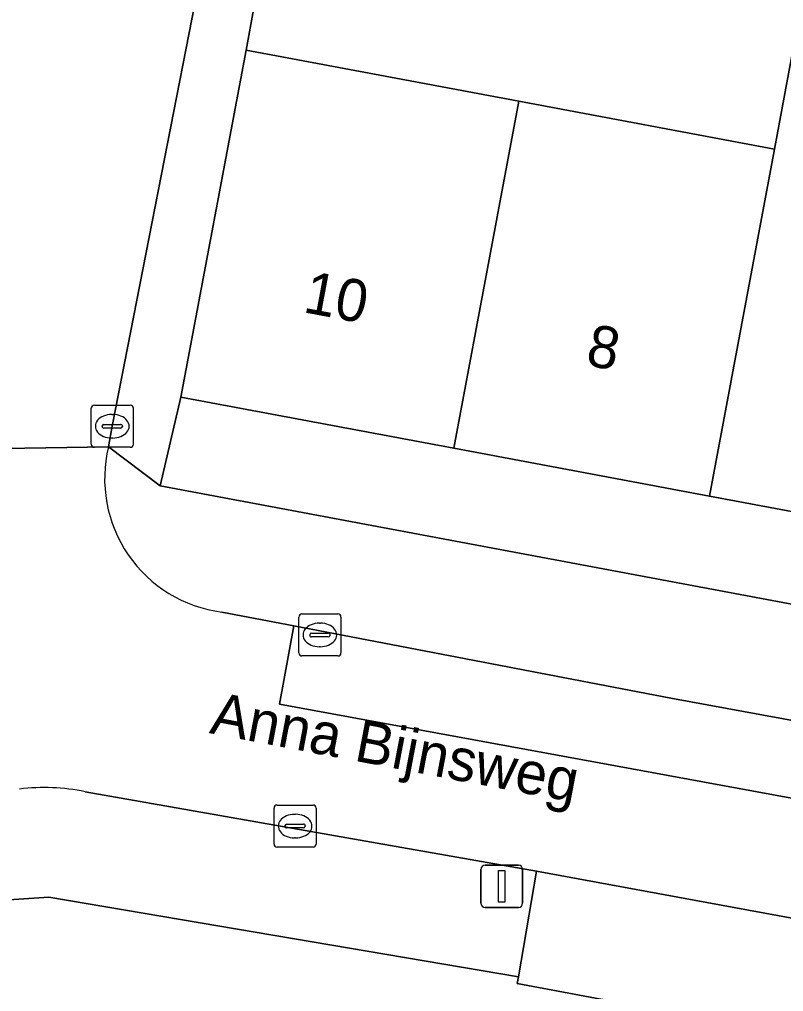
# Model space of a CAD drawing. Extents: x 161402 to 161933, y 381647 to 382315.
# Drawn here: x 161820.33 to 161838.49, y 381943.55 to 381966.66 of the extents above; entities that cross this region are included whole.
import ezdxf

# ---------------------------------------------------------------- set-up
doc = ezdxf.new("R2010")
doc.units = 0
for name, color, linetype in [('IMGEO_Erf', 7, 'Continuous'), ('IMGEO_Kolk', 7, 'Continuous'), ('IMGEO_Lichtmast', 7, 'Continuous'), ('IMGEO_Muur', 7, 'Continuous'), ('IMGEO_Openbare_ruimte_label', 7, 'Continuous'), ('IMGEO_Pand', 7, 'Continuous'), ('IMGEO_Pand_nummerreeks', 7, 'Continuous'), ('IMGEO_Parkeervlak_open', 7, 'Continuous'), ('IMGEO_Rijbaan_lokaal_open', 7, 'Continuous'), ('IMGEO_Voetpad_open', 7, 'Continuous')]:
    doc.layers.add(name, color=color, linetype=linetype)

msp = doc.modelspace()

# ---------------------------------------------------------------- linework, layer by layer
at = {"layer": 'IMGEO_Erf'}
for points in [[(161839.466, 381979.518), (161834.946, 381980.346), (161834.257, 381976.588), (161827.883, 381977.756), (161826.684, 381971.203), (161825.719, 381965.932), (161832.204, 381964.716), (161838.276, 381963.578), (161838.779, 381966.265)], [(161842.923, 381954.168), (161836.731, 381955.328), (161830.659, 381956.466), (161824.173, 381957.682), (161823.681, 381955.575), (161857.033, 381949.323)], [(161842.874, 381941.733), (161832.159, 381943.741), (161832.192, 381943.9), (161821.03, 381945.795), (161819.839, 381945.717), (161811.12, 381943.457)]]:
    msp.add_lwpolyline(points, dxfattribs=at)
at = {"layer": 'IMGEO_Kolk'}
for p, q in [((161822.039, 381956.565), (161822.039, 381957.417)), ((161822.114, 381957.491), (161822.966, 381957.491)), ((161823.04, 381957.417), (161823.04, 381956.565)), ((161822.527, 381957.271), (161822.552, 381957.271)), ((161822.298, 381956.985), (161822.298, 381956.997)), ((161822.736, 381956.948), (161822.338, 381956.948)), ((161822.341, 381957.034), (161822.739, 381957.034)), ((161822.782, 381956.997), (161822.782, 381956.985)), ((161822.55, 381956.711), (161822.525, 381956.711)), ((161822.966, 381956.491), (161822.114, 381956.491)), ((161827.048, 381952.529), (161827.9, 381952.529)), ((161826.973, 381951.603), (161826.973, 381952.455)), ((161827.461, 381952.309), (161827.486, 381952.309)), ((161827.974, 381952.455), (161827.974, 381951.603)), ((161827.232, 381952.023), (161827.232, 381952.035)), ((161827.275, 381952.072), (161827.673, 381952.072)), ((161827.716, 381952.035), (161827.716, 381952.023)), ((161827.67, 381951.986), (161827.272, 381951.986)), ((161827.484, 381951.749), (161827.459, 381951.749)), ((161827.9, 381951.529), (161827.048, 381951.529)), ((161826.384, 381947.058), (161826.384, 381947.91)), ((161826.459, 381947.984), (161827.311, 381947.984)), ((161827.385, 381947.91), (161827.385, 381947.058)), ((161826.872, 381947.764), (161826.897, 381947.764)), ((161826.643, 381947.478), (161826.643, 381947.49)), ((161827.081, 381947.441), (161826.683, 381947.441)), ((161826.686, 381947.527), (161827.084, 381947.527)), ((161827.127, 381947.49), (161827.127, 381947.478)), ((161826.895, 381947.204), (161826.87, 381947.204)), ((161827.311, 381946.984), (161826.459, 381946.984))]:
    msp.add_line(p, q, dxfattribs=at)
for points in [[(161822.039, 381956.565), (161822.039, 381957.417)], [(161822.114, 381957.491), (161822.966, 381957.491)], [(161823.04, 381957.417), (161823.04, 381956.565)], [(161822.966, 381956.491), (161822.114, 381956.491)], [(161827.048, 381952.529), (161827.9, 381952.529)], [(161826.973, 381951.603), (161826.973, 381952.455)], [(161827.974, 381952.455), (161827.974, 381951.603)], [(161827.9, 381951.529), (161827.048, 381951.529)], [(161826.384, 381947.058), (161826.384, 381947.91)], [(161826.459, 381947.984), (161827.311, 381947.984)], [(161827.385, 381947.91), (161827.385, 381947.058)], [(161827.311, 381946.984), (161826.459, 381946.984)]]:
    msp.add_lwpolyline(points, dxfattribs=at)
for centre, radius, start, end in [((161822.116, 381957.415), 0.0765, 91.552, 178.448), ((161822.116, 381957.415), 0.0765, 91.552, 178.448), ((161822.964, 381957.415), 0.0765, 1.552, 88.448), ((161822.964, 381957.415), 0.0765, 1.552, 88.448), ((161822.338, 381956.994), 0.0403, 85.8775, 175.7526), ((161822.335, 381956.984), 0.0366, 178.938, 274.7102), ((161822.739, 381956.991), 0.043, 264.8664, 352.4533), ((161822.743, 381956.996), 0.0386, 1.7309, 96.639), ((161822.116, 381956.567), 0.0765, 181.552, 268.448), ((161822.116, 381956.567), 0.0765, 181.552, 268.448), ((161822.964, 381956.567), 0.0765, 271.552, 358.448), ((161822.964, 381956.567), 0.0765, 271.552, 358.448), ((161827.05, 381952.453), 0.0765, 91.552, 178.448), ((161827.05, 381952.453), 0.0765, 91.552, 178.448), ((161827.898, 381952.453), 0.0765, 1.552, 88.448), ((161827.898, 381952.453), 0.0765, 1.552, 88.448), ((161827.272, 381952.032), 0.0403, 85.8775, 175.7526), ((161827.269, 381952.022), 0.0366, 178.938, 274.7102), ((161827.673, 381952.029), 0.043, 264.8664, 352.4533), ((161827.677, 381952.034), 0.0386, 1.7309, 96.639), ((161827.05, 381951.605), 0.0765, 181.552, 268.448), ((161827.05, 381951.605), 0.0765, 181.552, 268.448), ((161827.898, 381951.605), 0.0765, 271.552, 358.448), ((161827.898, 381951.605), 0.0765, 271.552, 358.448), ((161826.461, 381947.908), 0.0765, 91.552, 178.448), ((161826.461, 381947.908), 0.0765, 91.552, 178.448), ((161827.309, 381947.908), 0.0765, 1.552, 88.448), ((161827.309, 381947.908), 0.0765, 1.552, 88.448), ((161826.683, 381947.487), 0.0403, 85.8775, 175.7526), ((161826.68, 381947.477), 0.0366, 178.938, 274.7102), ((161827.084, 381947.484), 0.043, 264.8664, 352.4533), ((161827.088, 381947.489), 0.0386, 1.7309, 96.639), ((161826.461, 381947.06), 0.0765, 181.552, 268.448), ((161826.461, 381947.06), 0.0765, 181.552, 268.448), ((161827.309, 381947.06), 0.0765, 271.552, 358.448), ((161827.309, 381947.06), 0.0765, 271.552, 358.448)]:
    msp.add_arc(centre, radius, start, end, dxfattribs=at)
for centre, major_axis, ratio, start_param, end_param in [((161822.526, 381956.991), (-0.387, 0.002), 0.722429, 4.712389, 7.853982), ((161822.551, 381956.991), (-0.39, 0.002), 0.717154, 1.570796, 4.712389), ((161827.46, 381952.029), (-0.387, 0.002), 0.722429, 4.712389, 7.853982), ((161827.485, 381952.029), (-0.39, 0.002), 0.717154, 1.570796, 4.712389), ((161826.871, 381947.484), (-0.387, 0.002), 0.722429, 4.712389, 7.853982), ((161826.896, 381947.484), (-0.39, 0.002), 0.717154, 1.570796, 4.712389)]:
    msp.add_ellipse(centre, major_axis=major_axis, ratio=ratio, start_param=start_param, end_param=end_param, dxfattribs=at)
at = {"layer": 'IMGEO_Lichtmast'}
for p, q in [((161831.401, 381946.552), (161832.191, 381946.552)), ((161832.191, 381946.552), (161831.401, 381946.552)), ((161831.301, 381945.652), (161831.301, 381946.452)), ((161831.301, 381946.452), (161831.301, 381945.652)), ((161832.291, 381946.452), (161832.291, 381945.652)), ((161832.291, 381945.652), (161832.291, 381946.452)), ((161832.191, 381945.552), (161831.401, 381945.552)), ((161831.401, 381945.552), (161832.191, 381945.552))]:
    msp.add_line(p, q, dxfattribs=at)
msp.add_lwpolyline([(161831.721, 381946.427), (161831.871, 381946.427), (161831.871, 381945.677), (161831.721, 381945.677), (161831.721, 381946.427)], dxfattribs=at)
for centre, start, end in [((161831.401, 381946.452), 90, 180), ((161831.401, 381946.452), 90, 180), ((161832.191, 381946.452), 0, 90), ((161832.191, 381946.452), 360, 90), ((161831.401, 381945.652), 180, 270), ((161831.401, 381945.652), 180, 270), ((161832.191, 381945.652), 270, 0), ((161832.191, 381945.652), 270, 0)]:
    msp.add_arc(centre, 0.1, start, end, dxfattribs=at)
at = {"layer": 'IMGEO_Muur'}
msp.add_lwpolyline([(161826.684, 381971.203), (161825.719, 381965.932)], dxfattribs=at)
at = {"layer": 'IMGEO_Pand'}
for points in [[(161836.731, 381955.328), (161842.923, 381954.168), (161844.971, 381965.105), (161838.779, 381966.265), (161838.276, 381963.578)], [(161830.659, 381956.466), (161832.204, 381964.716), (161825.719, 381965.932), (161824.173, 381957.682)], [(161836.731, 381955.328), (161838.276, 381963.578), (161832.204, 381964.716), (161830.659, 381956.466)]]:
    msp.add_lwpolyline(points, close=True, dxfattribs=at)
at = {"layer": 'IMGEO_Parkeervlak_open'}
msp.add_lwpolyline([(161835.816, 381950.524), (161826.853, 381952.245), (161826.511, 381950.381), (161841.229, 381947.681), (161841.561, 381949.474)], close=True, dxfattribs=at)
at = {"layer": 'IMGEO_Rijbaan_lokaal_open'}
for points in [[(161859.869, 382107.508), (161855.583, 382102.928), (161847.522, 382094.137), (161844.797, 382079.199), (161841.729, 382061.924), (161839.275, 382047.946), (161836.784, 382033.46), (161833.899, 382016.966), (161830.695, 382000), (161827.554, 381983.498), (161825.196, 381970.616), (161825.164, 381970.44), (161822.54, 381956.991), (161822.45, 381956.505), (161823.681, 381955.575), (161824.173, 381957.682), (161825.719, 381965.932), (161826.684, 381971.203), (161827.883, 381977.756), (161828.609, 381981.506), (161828.968, 381983.243), (161830.987, 381994.574), (161831.954, 382000), (161840.202, 382046.042)], [(161830.73, 382029.273), (161829.195, 382020.232), (161827.39, 382010.57), (161825.499, 382000), (161825.157, 381998.089), (161824.386, 381993.913), (161817.254, 381957.834), (161817.094, 381956.896), (161816.977, 381956.412), (161822.45, 381956.505), (161822.54, 381956.991), (161825.164, 381970.44), (161825.196, 381970.616), (161827.554, 381983.498), (161830.695, 382000), (161833.899, 382016.966), (161836.784, 382033.46)], [(161822.45, 381956.505), (161816.977, 381956.412)], [(161826.853, 381952.245), (161825.144, 381952.573)], [(161821.896, 381948.301), (161832.624, 381946.415), (161840.719, 381944.921), (161841.229, 381947.681), (161826.511, 381950.381), (161826.853, 381952.245)]]:
    msp.add_lwpolyline(points, dxfattribs=at)
for centre, radius, start, end in [((161825.556, 381955.744), 3.198, 166.2409, 262.5929), ((161820.924, 381943.604), 4.796, 78.3111, 97.0695)]:
    msp.add_arc(centre, radius, start, end, dxfattribs=at)
at = {"layer": 'IMGEO_Voetpad_open'}
for points in [[(161861.825, 381948.441), (161857.033, 381949.323), (161823.681, 381955.575), (161822.45, 381956.505)], [(161825.144, 381952.573), (161826.853, 381952.245), (161835.816, 381950.524), (161841.561, 381949.474), (161844.266, 381948.98), (161844.817, 381948.879), (161850.705, 381947.765), (161856.849, 381946.602), (161856.934, 381947.094), (161867.35, 381945.192), (161867.265, 381944.7), (161868.335, 381944.505), (161870.982, 381944.038), (161878.707, 381942.675), (161882.65, 381941.962), (161882.997, 381941.882), (161884.023, 381941.644), (161884.434, 381944.363)], [(161811.12, 381943.457), (161819.839, 381945.717), (161821.03, 381945.795), (161832.192, 381943.9), (161832.624, 381946.415), (161821.896, 381948.301)]]:
    msp.add_lwpolyline(points, dxfattribs=at)
msp.add_lwpolyline([(161840.719, 381944.921), (161832.624, 381946.415), (161832.192, 381943.9), (161832.159, 381943.741), (161842.874, 381941.733), (161843.358, 381944.434)], close=True, dxfattribs=at)
for centre, radius, start, end in [((161825.556, 381955.744), 3.198, 166.2409, 262.5929), ((161820.924, 381943.604), 4.796, 78.3111, 97.0695)]:
    msp.add_arc(centre, radius, start, end, dxfattribs=at)

# ---------------------------------------------------------------- texts
at = {"layer": 'IMGEO_Openbare_ruimte_label'}
msp.add_text('Anna Bijnsweg', height=1, rotation=349.2184, dxfattribs=at).set_placement((161824.828, 381949.697))
at = {"layer": 'IMGEO_Pand_nummerreeks'}
for s, p in [('10', (161827.048, 381959.707)), ('8', (161833.764, 381958.448))]:
    msp.add_text(s, height=1, rotation=349.3843, dxfattribs=at).set_placement(p)

doc.saveas('drawing.dxf')
